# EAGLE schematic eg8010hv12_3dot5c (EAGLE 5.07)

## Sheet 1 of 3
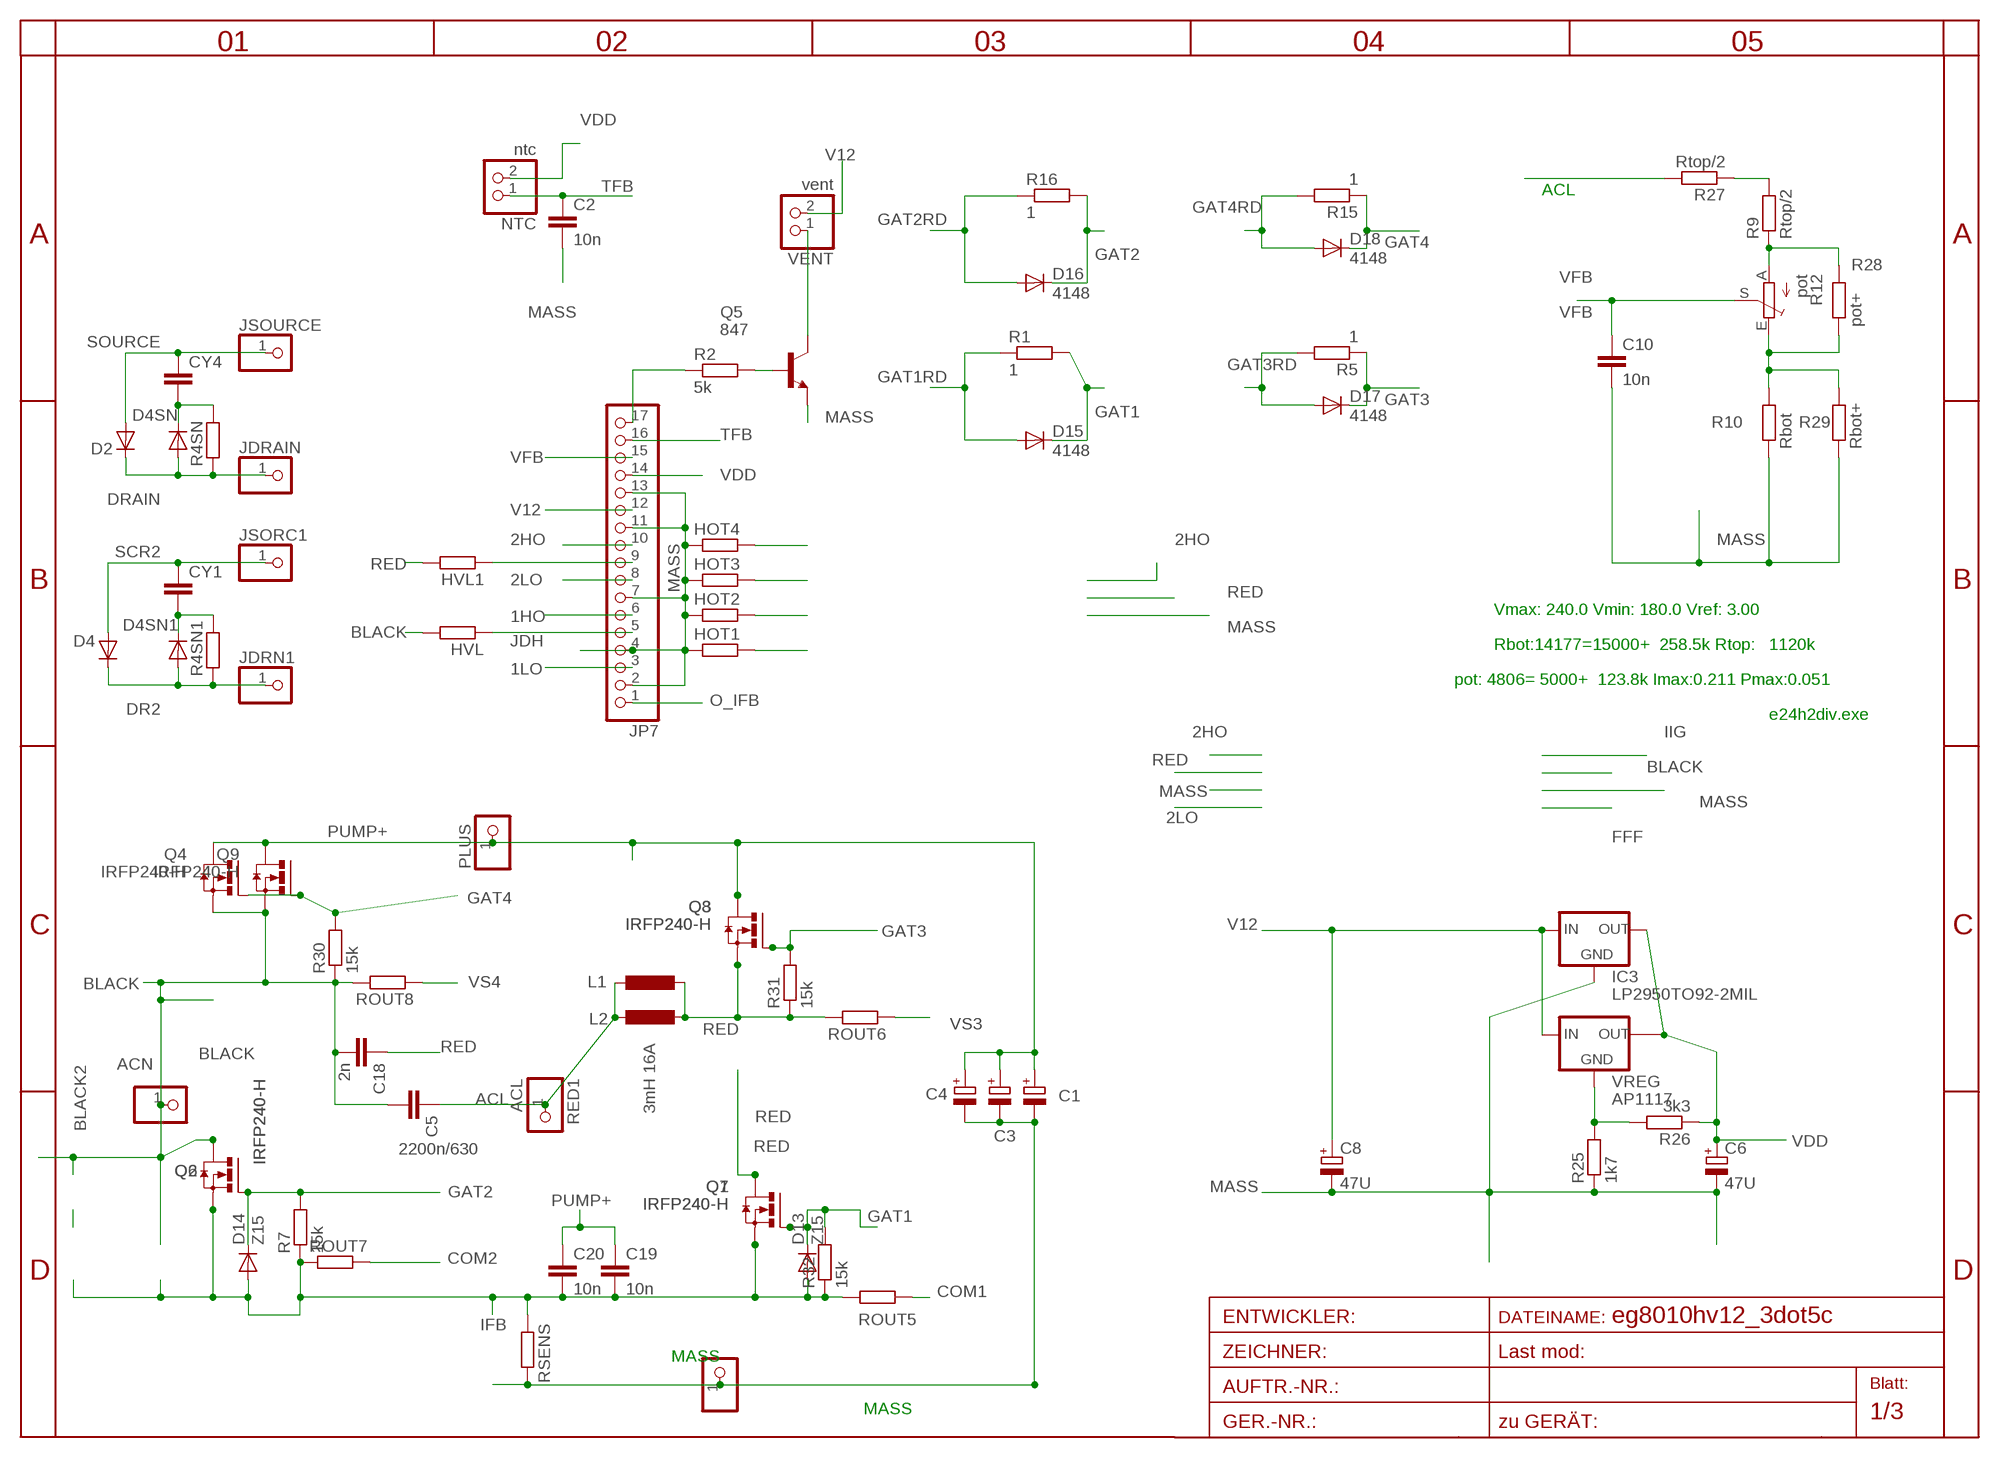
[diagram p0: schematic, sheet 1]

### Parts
BLACK2  ACN  PINHD-1X12MM3  [1X2MM3]
C1  CPOL-EUE5-13  [E5-13]
C2  10n  C-EUC0805  [C0805]
C3  CPOL-EUE5-13  [E5-13]
C4  CPOL-EUE5-13  [E5-13]
C5  2200n/630  C-EU275-173X316  [C275-173X316]
C6  47U  CPOL-EUSMCA  [SMC_A]
C8  47U  CPOL-EUSMCA  [SMC_A]
C10  10n  C-EUC0805  [C0805]
C18  2n  C-EU050-024X044  [C050-024X044]
C19  10n  C-EU050-024X044  [C050-024X044]
C20  10n  C-EU050-024X044  [C050-024X044]
CY1  CXXC10B5  [XC10B5]
CY4  CXXC10B5  [XC10B5]
D2  DIODE-SMC  [SMC]
D4  DIODE-SMC  [SMC]
D4SN  DIODE-P1-10  [P1-10]
D4SN1  DIODE-P1-10  [P1-10]
D13  Z15  DIODE-MINIMELF  [MINIMELF]
D14  Z15  DIODE-MINIMELF  [MINIMELF]
D15  4148  DIODE-MINIMELF  [MINIMELF]
D16  4148  DIODE-MINIMELF  [MINIMELF]
D17  4148  DIODE-MINIMELF  [MINIMELF]
D18  4148  DIODE-MINIMELF  [MINIMELF]
HOT1  R-EU_R0805  [R0805]
HOT2  R-EU_R0805  [R0805]
HOT3  R-EU_R0805  [R0805]
HOT4  R-EU_R0805  [R0805]
HVL  R-EU_R1005  [R1005]
HVL1  R-EU_R1005  [R1005]
IC3  LP2950TO92-2MIL  [TO92-2MIL]
JDRAIN  PINHD-1X11MM0  [1X1MM0]
JDRN1  PINHD-1X11MM0  [1X1MM0]
JP7  PINHD-1X17  [1X17]
JSORC1  PINHD-1X11MM0  [1X1MM0]
JSOURCE  PINHD-1X11MM0  [1X1MM0]
L1  L-EU4.13  [0204/13]
L2  3mH 16A  L-EURNG  [RING]
MINUS  PINHD-1X12MM3  [1X2MM3]
NTC  ntc  PINHD-1X2STR  [1X02]
PLUS  PINHD-1X12MM3  [1X2MM3]
Q1  IRFP240-H  [TO247BH]
Q2  IRFP240-H  [TO247BH]
Q3  IRFP240-H  [TO247BH]
Q4  IRFP240-H  [TO247BH]
Q5  847  BC847SMD  [SOT23]
Q6  IRFP240-H  [TO247BH]
Q7  IRFP240-H  [TO247BH]
Q8  IRFP240-H  [TO247BH]
Q9  IRFP240-H  [TO247BH]
R1  1  R-EU_R2512  [R2512]
R2  5k  R-EU_R0805  [R0805]
R4SN  R-EU_0207/10  [0207/10]
R4SN1  R-EU_0207/10  [0207/10]
R5  1  R-EU_R2512  [R2512]
R7  15k  R-EU_R1206  [R1206]
R9  Rtop/2  R-EU_R1206  [R1206]
R10  Rbot  R-EU_R0805  [R0805]
R12  pot  TRIM_EU-B64Y  [B64Y]
R15  1  R-EU_R2512  [R2512]
R16  1  R-EU_R2512  [R2512]
R25  1k7  R-EU_R0805  [R0805]
R26  3k3  R-EU_R0805  [R0805]
R27  Rtop/2  R-EU_R1206  [R1206]
R28  pot+  R-EU_R0805  [R0805]
R29  Rbot+  R-EU_R0805  [R0805]
R30  15k  R-EU_R1206  [R1206]
R31  15k  R-EU_R1206  [R1206]
R32  15k  R-EU_R1206  [R1206]
RED1  ACL  PINHD-1X12MM3  [1X2MM3]
ROUT5  R-EU_R2512  [R2512]
ROUT6  R-EU_R2512  [R2512]
ROUT7  R-EU_R2512  [R2512]
ROUT8  R-EU_R2512  [R2512]
RSENS  R-EU_WIRE  [WIRE]
VENT  vent  PINHD-1X2STR  [1X02]
VREG  AP1117  [SOT223]

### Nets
1HO: HOT2.2 JP7.6 ; also sheet 3
1LO: HOT1.2 JP7.3 ; also sheet 3
2HO: HOT4.2 JP7.10 ; also sheet 3
2LO: HOT3.2 JP7.8 ; also sheet 3
ACL: C5.1 L1.1 L2.2 R27.2 RED1.1
BLACK: BLACK2.1 C5.2 C18.2 HVL.2 Q2.D Q4.S Q6.D Q9.S R30.1 ROUT8.2
COM1: ROUT5.1 ; also sheet 3
COM2: ROUT7.2 ; also sheet 3
DFG: HVL1.1 JP7.9
DR2: D4.C D4SN1.A JDRN1.1 R4SN1.1
DRAIN: D2.C D4SN.A JDRAIN.1 R4SN.1
GAT1: D13.C D15.C Q1.G Q7.G R1.2 R32.2
GAT1RD: D15.A R1.1 ; also sheet 3
GAT2: D14.C D16.C Q2.G Q6.G R7.2 R16.2
GAT2RD: D16.A R16.1 ; also sheet 3
GAT3: D17.C Q3.G Q8.G R5.1 R31.2
GAT3RD: D17.A R5.2 ; also sheet 3
GAT4: D18.C Q4.G Q9.G R15.1 R30.2
GAT4RD: D18.A R15.2 ; also sheet 3
IFB: C19.2 C20.2 D13.A D14.A Q1.S Q2.S Q6.S Q7.S R7.1 R32.1 ROUT5.2 ROUT7.1 RSENS.1 ; also sheet 2,3
JDH: HVL.1 JP7.5
MASS: C1.- C2.2 C3.- C4.- C6.- C8.- C10.2 HOT1.1 HOT2.1 HOT3.1 HOT4.1 IC3.2(GND) JP7.2 JP7.4 JP7.7 JP7.11 JP7.13 MINUS.1 Q5.2(E) R10.1 R25.1 R29.1 RSENS.2 ; also sheet 2,3
N$1: Q5.3(C) VENT.1
N$2: Q5.1(B) R2.2
N$3: JP7.17 R2.1
N$17: R25.2 R26.2 VREG.1(GND)
N$23: R9.2 R27.1
N$29: R10.2 R12.E R28.1 R29.2
N$30: R9.1 R12.A R28.2
O_IFB: JP7.1 ; also sheet 3
PUMP+: C1.+ C3.+ C4.+ C19.1 C20.1 PLUS.1 Q3.D Q4.D Q8.D Q9.D ; also sheet 2
RED: C18.1 HVL1.2 L1.2 L2.1 Q1.D Q3.S Q7.D Q8.S R31.1 ROUT6.2
SCR2: CY1.1 D4.A JSORC1.1
SNUB1: CY1.2 D4SN1.C R4SN1.2
SNUB2: CY4.2 D4SN.C R4SN.2
SOURCE: CY4.1 D2.A JSOURCE.1
TFB: C2.1 JP7.16 NTC.1 ; also sheet 2
V12: C8.+ IC3.3(IN) JP7.12 VENT.2 VREG.3(IN) ; also sheet 2,3
VDD: C6.+ IC3.1(OUT) JP7.14 NTC.2 R26.1 VREG.4(TAB) ; also sheet 2
VFB: C10.1 JP7.15 R12.S ; also sheet 2
VS3: ROUT6.1
VS4: ROUT8.1 ; also sheet 3
Unconnected: VREG.2(OUT)

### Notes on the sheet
- Vmax: 240.0 Vmin: 180.0 Vref: 3.00
- Rbot:14177=15000+  258.5k Rtop:   1120k
- pot: 4806= 5000+  123.8k Imax:0.211 Pmax:0.051
- e24h2div.exe

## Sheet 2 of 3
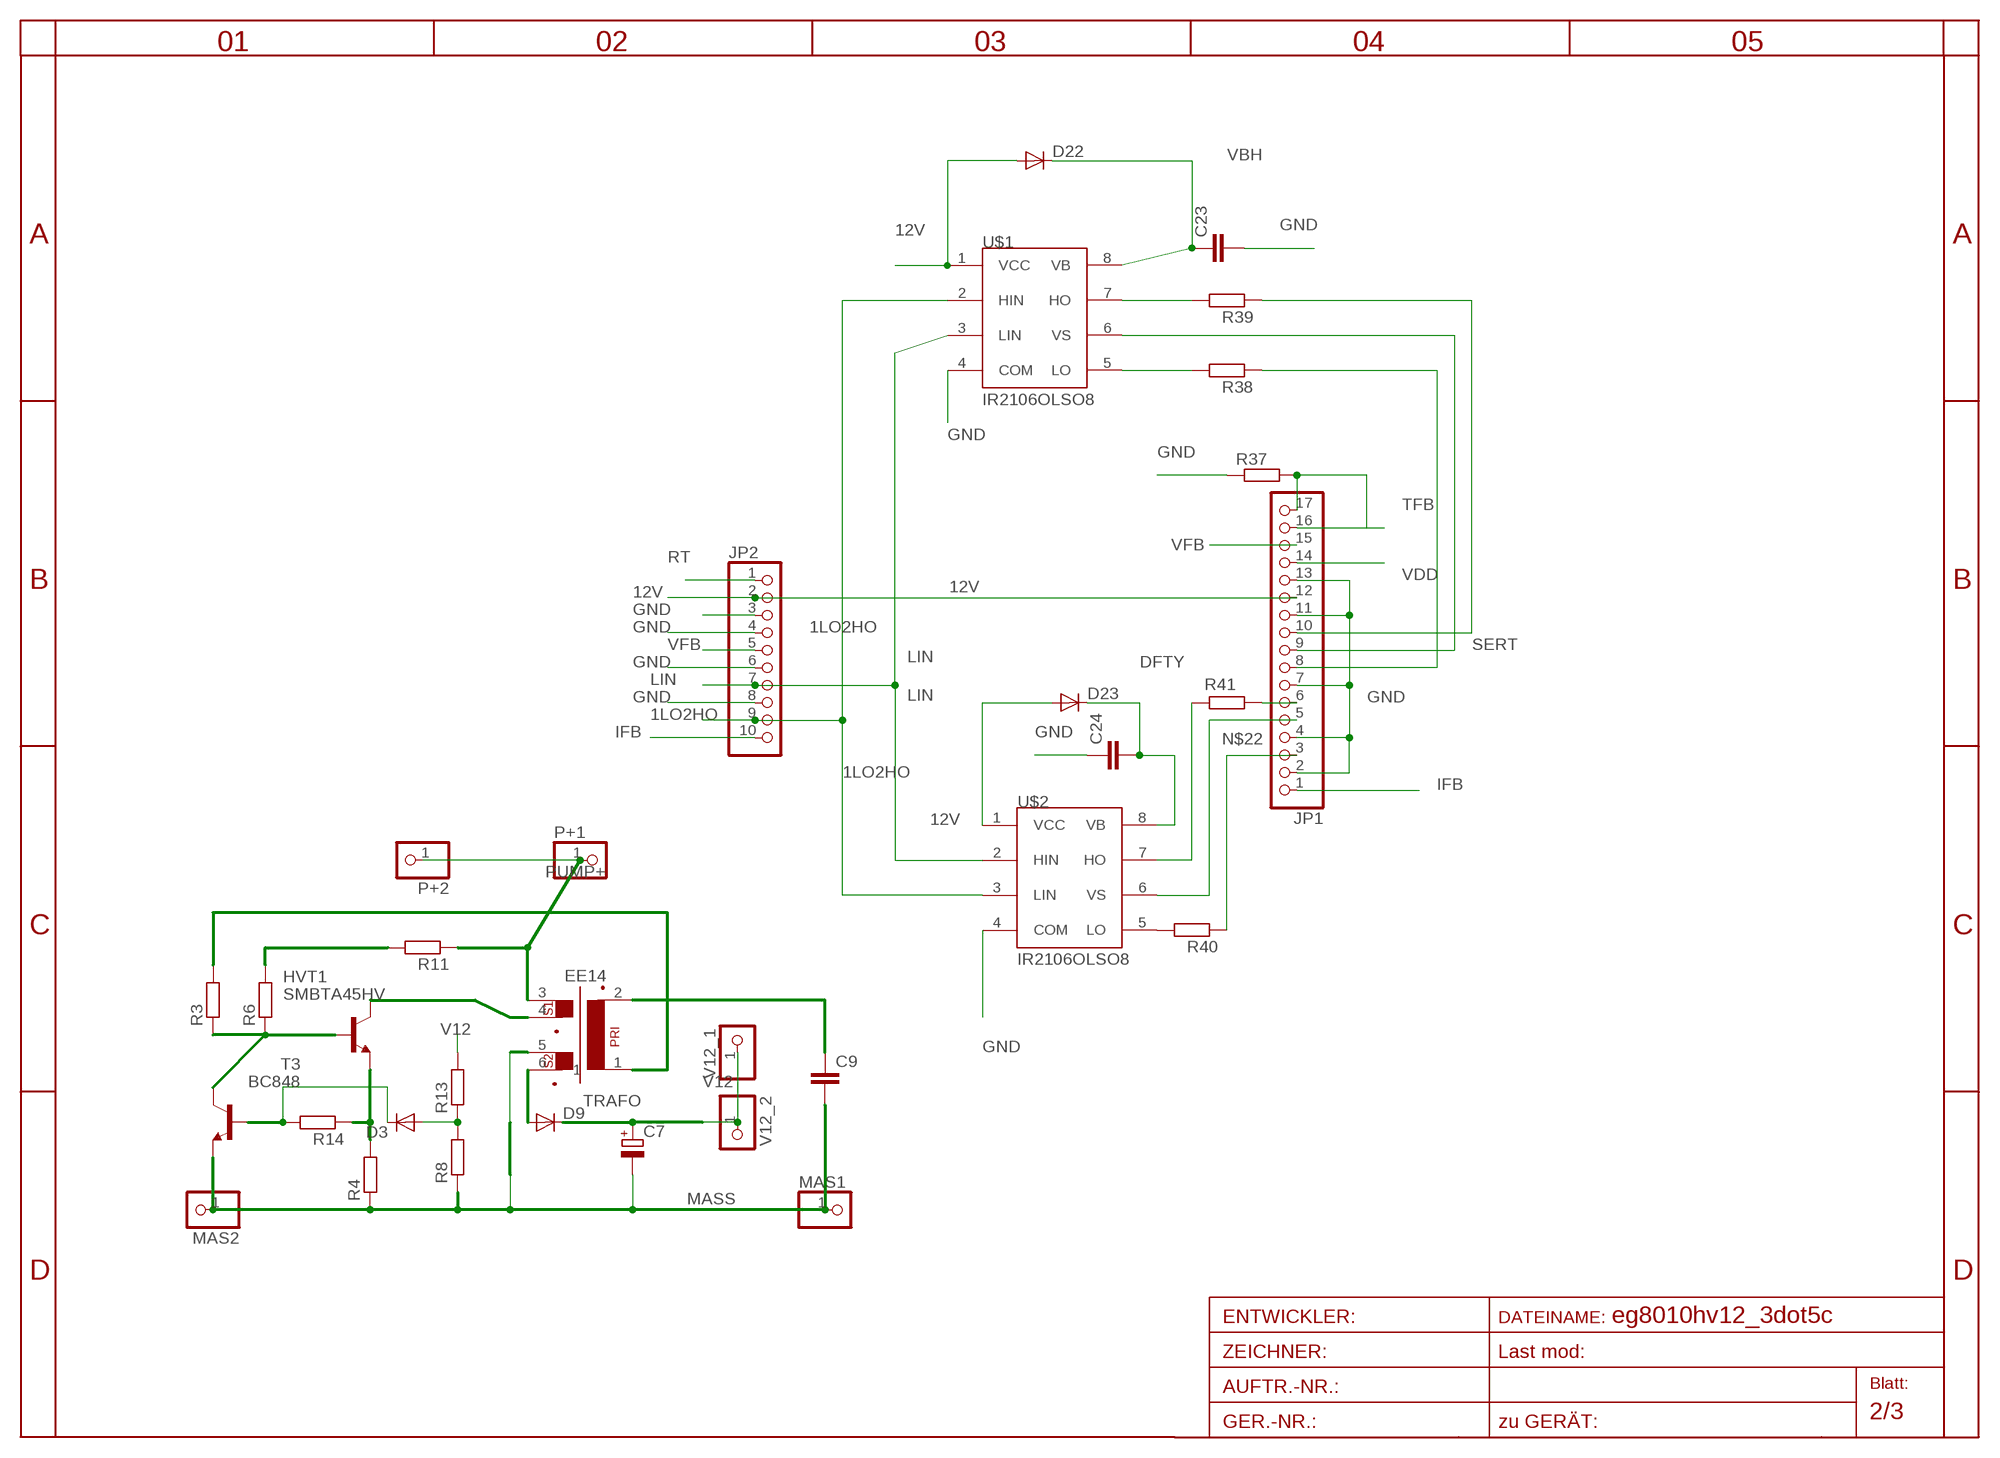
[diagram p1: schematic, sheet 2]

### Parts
C7  CPOL-EUSMCA  [SMC_A]
C9  C-EUC0805  [C0805]
C23  C-EUC1206  [C1206]
C24  C-EUC1206  [C1206]
D3  DIODE-MINIMELF  [MINIMELF]
D9  DIODE-SMA-DO214  [SMA-DO214AC]
D22  DIODE-SMA-DO214  [SMA-DO214AC]
D23  DIODE-SMA-DO214  [SMA-DO214AC]
HVT1  SMBTA45HV  [SOT23HV]
JP1  PINHD-1X17  [1X17]
JP2  PINHD-1X100X05  [1X10]
MAS1  PINHD-1X11X0.4  [1X01]
MAS2  PINHD-1X11X0.4  [1X01]
P+1  PINHD-1X11X0.4  [1X01]
P+2  PINHD-1X11X0.4  [1X01]
R3  R-EU_R0805  [R0805]
R4  R-EU_R0805  [R0805]
R6  R-EU_R1206  [R1206]
R8  R-EU_R0805  [R0805]
R11  R-EU_R1206  [R1206]
R13  R-EU_R0805  [R0805]
R14  R-EU_R0805  [R0805]
R37  R-EU_0204/2V  [0204V]
R38  R-EU_0204/2V  [0204V]
R39  R-EU_0204/2V  [0204V]
R40  R-EU_0204/2V  [0204V]
R41  R-EU_0204/2V  [0204V]
T3  BC848  [SOT23]
TRAFO  EE14  [EE14]
U$1  IR2106OLSO8  [SO8-2]
U$2  IR2106OLSO8  [SO8-2]
V12_1  PINHD-1X11X0.4  [1X01]
V12_2  PINHD-1X11X0.4  [1X01]

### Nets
1LO2HO: JP2.9 U$1.2(HIN) U$2.3(LIN)
12V: D22.A D23.A JP1.12 JP2.2 U$1.1(VCC) U$2.1(VCC)
A: D9.A TRAFO.6
B1C2: HVT1.1(B) R3.1 R6.1 T3.C
BT1: D3.C R14.2 T3.B
C1: HVT1.3(C) TRAFO.4
DFTY: C24.2 D23.K(C) U$2.8(VB)
EB: HVT1.2(E) R4.2 R14.1
GND: C23.2 C24.1 JP1.2 JP1.4 JP1.7 JP1.11 JP1.13 JP2.3 JP2.4 JP2.6 JP2.8 R37.1 U$1.4(COM) U$2.4(COM)
IFB: JP1.1 JP2.10 ; also sheet 1,3
LIN: JP2.7 U$1.3(LIN) U$2.2(HIN)
MASS: C7.- C9.2 MAS1.1 MAS2.1 R4.1 R8.1 T3.E TRAFO.5 ; also sheet 1,3
N$6: R3.2 TRAFO.1
N$7: C9.1 TRAFO.2
N$8: R6.2 R11.2
N$10: D3.A R8.2 R13.1
N$15: JP1.3 R40.1
N$19: R41.2 U$2.7(HO)
N$21: JP1.8 R38.1
N$22: JP1.5 U$2.6(VS)
N$27: JP1.10 R39.1
N$32: R38.2 U$1.5(LO)
N$33: R39.2 U$1.7(HO)
N$34: JP1.6 R41.1
N$35: R40.2 U$2.5(LO)
PUMP+: P+1.1 P+2.1 R11.1 TRAFO.3 ; also sheet 1
RT: JP2.1
SERT: JP1.9 U$1.6(VS)
TFB: JP1.16 JP1.17 R37.2 ; also sheet 1
V12: C7.+ D9.K(C) R13.2 V12_1.1 V12_2.1 ; also sheet 1,3
VBH: C23.1 D22.K(C) U$1.8(VB)
VDD: JP1.14 ; also sheet 1
VFB: JP1.15 JP2.5 ; also sheet 1

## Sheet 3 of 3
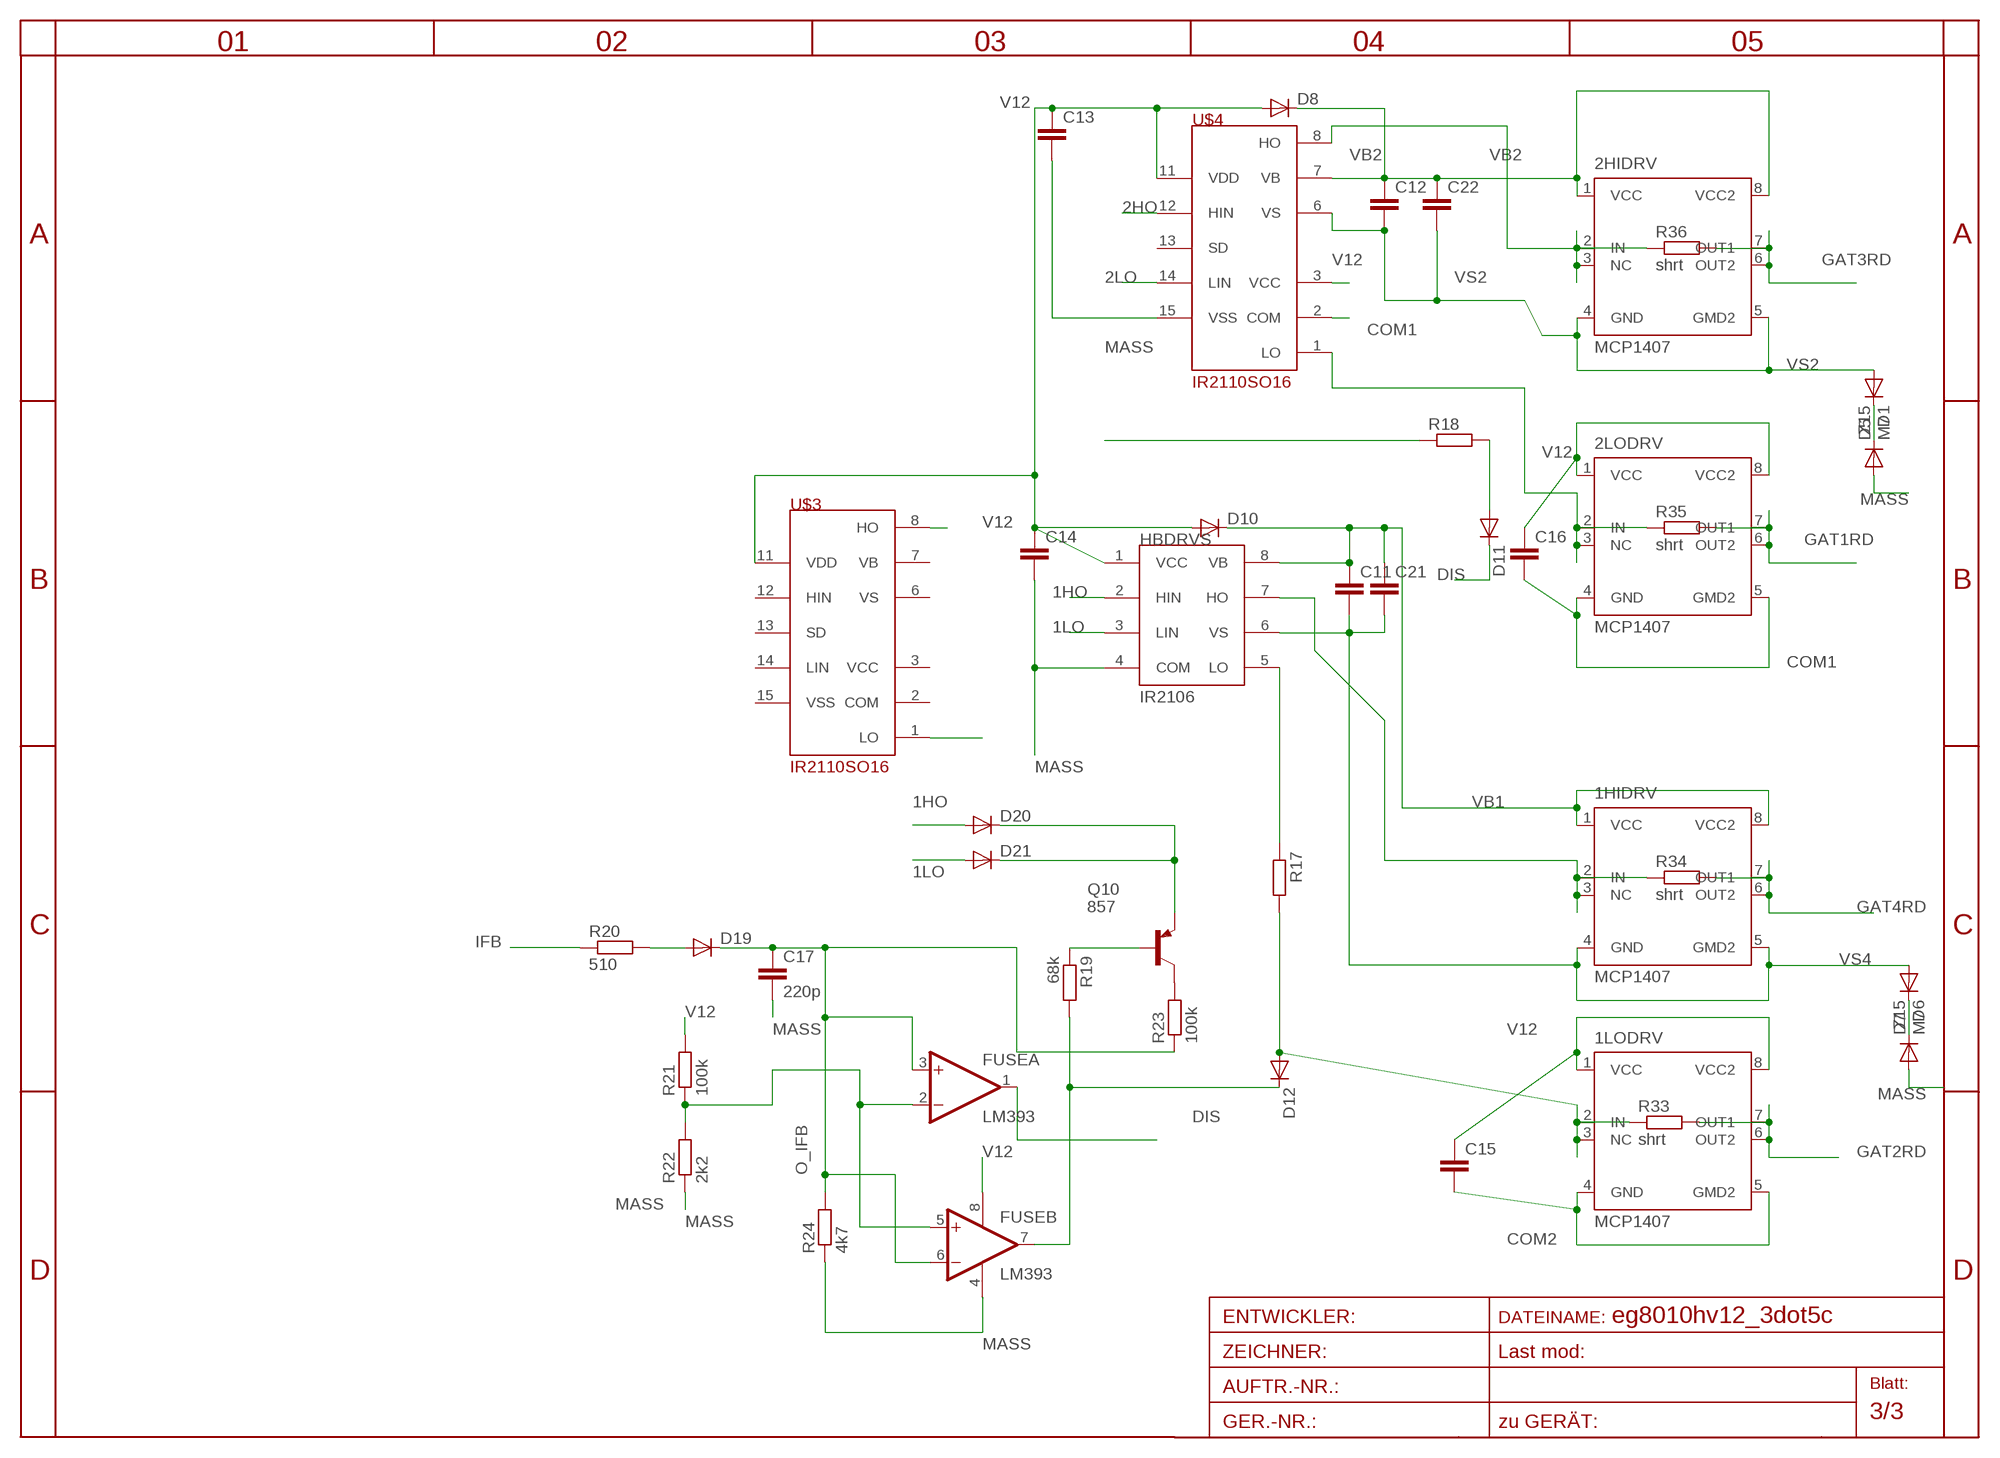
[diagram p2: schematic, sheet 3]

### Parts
1HIDRV  MCP1407  [SO-08M]
1LODRV  MCP1407  [SO-08M]
2HIDRV  MCP1407  [SO-08M]
2LODRV  MCP1407  [SO-08M]
C11  C-EUC058MLCC  [C058-020X040]
C12  C-EUC058MLCC  [C058-020X040]
C13  C-EUC1206  [C1206]
C14  C-EUC1206  [C1206]
C15  C-EUC1206  [C1206]
C16  C-EUC1206  [C1206]
C17  220p  C-EUC0805  [C0805]
C21  C-EUC1206  [C1206]
C22  C-EUC1206  [C1206]
D1  Z15  DIODE-MINIMELF  [MINIMELF]
D5  M7  DIODE-SMA-DO214  [SMA-DO214AC]
D6  Z15  DIODE-MINIMELF  [MINIMELF]
D7  M7  DIODE-SMA-DO214  [SMA-DO214AC]
D8  DIODE-SMA-DO214  [SMA-DO214AC]
D10  DIODE-SMA-DO214  [SMA-DO214AC]
D11  DIODE-MINIMELF  [MINIMELF]
D12  DIODE-MINIMELF  [MINIMELF]
D19  DIODE-SOT23  [SOT23]
D20  DIODE-SOT23  [SOT23]
D21  DIODE-SOT23  [SOT23]
FUSE  LM393  LM358D  [SO08]
HBDRVS  IR2106  [SO8-5]
Q10  857  BC857ALT1SMD  [SOT23-BEC]
R17  R-EU_0207-17  [0207/17]
R18  R-EU_0204/5  [0204/5]
R19  68k  R-EU_R0805  [R0805]
R20  510  R-EU_R0805  [R0805]
R21  100k  R-EU_R0805  [R0805]
R22  2k2  R-EU_R0805  [R0805]
R23  100k  R-EU_R0805  [R0805]
R24  4k7  R-EU_R0805  [R0805]
R33  shrt  R-EU_R1206  [R1206]
R34  shrt  R-EU_R1206  [R1206]
R35  shrt  R-EU_R1206  [R1206]
R36  shrt  R-EU_R1206  [R1206]
U$3  IR2110SO16  [SO16DW]
U$4  IR2110SO16  [SO16DW]

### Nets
1HO: D20.1(A) HBDRVS.2(HIN) ; also sheet 1
1LO: D21.1(A) HBDRVS.3(LIN) ; also sheet 1
2HO: U$4.12(HIN) ; also sheet 1
2LO: U$4.14(LIN) ; also sheet 1
COM1: 2LODRV.4(GND) 2LODRV.5(GMD2) C16.2 U$4.2(COM) ; also sheet 1
COM2: 1LODRV.4(GND) 1LODRV.5(GMD2) C15.2 ; also sheet 1
DIS: D11.C D12.C FUSE.7(B:OUT) R19.2
GAT1RD: 2LODRV.6(OUT2) 2LODRV.7(OUT1) R35.2 ; also sheet 1
GAT2RD: 1LODRV.6(OUT2) 1LODRV.7(OUT1) R33.2 U$3.1(LO) ; also sheet 1
GAT3RD: 2HIDRV.6(OUT2) 2HIDRV.7(OUT1) R36.2 ; also sheet 1
GAT4RD: 1HIDRV.6(OUT2) 1HIDRV.7(OUT1) R34.2 U$3.8(HO) ; also sheet 1
IFB: R20.1 ; also sheet 1,2
MASS: C13.2 C14.2 C17.2 D5.A D7.A FUSE.4(P:V-) HBDRVS.4(COM) R22.1 R24.1 U$4.15(VSS) ; also sheet 1,2
N$4: R18.1
N$5: 1LODRV.2(IN) 1LODRV.3(NC) D12.A R17.2 R33.1
N$9: FUSE.2(A:-IN) FUSE.5(B:+IN) R21.1 R22.2
N$11: HBDRVS.5(LO) R17.1
N$12: 2HIDRV.2(IN) 2HIDRV.3(NC) R36.1 U$4.8(HO)
N$13: 1HIDRV.2(IN) 1HIDRV.3(NC) HBDRVS.7(HO) R34.1
N$14: D19.1(A) R20.2
N$16: 2LODRV.2(IN) 2LODRV.3(NC) R35.1 U$4.1(LO)
N$18: D20.3(C) D21.3(C) Q10.E
N$20: D1.C D5.K(C)
N$24: D6.C D7.K(C)
N$25: Q10.B R19.1
N$26: Q10.C R23.2
N$36: D11.A R18.2
O_IFB: C17.1 D19.3(C) FUSE.3(A:+IN) FUSE.6(B:-IN) R23.1 R24.2 ; also sheet 1
SD: FUSE.1(A:OUT)
V12: 1LODRV.1(VCC) 1LODRV.8(VCC2) 2LODRV.1(VCC) 2LODRV.8(VCC2) C13.1 C14.1 C15.1 C16.1 D8.A D10.A FUSE.8(P:V+) HBDRVS.1(VCC) R21.2 U$3.11(VDD) U$4.3(VCC) U$4.11(VDD) ; also sheet 1,2
VB1: 1HIDRV.1(VCC) 1HIDRV.8(VCC2) C11.1 C21.1 D10.K(C) HBDRVS.8(VB)
VB2: 2HIDRV.1(VCC) 2HIDRV.8(VCC2) C12.1 C22.1 D8.K(C) U$4.7(VB)
VS2: 2HIDRV.4(GND) 2HIDRV.5(GMD2) C12.2 C22.2 D1.A U$4.6(VS)
VS4: 1HIDRV.4(GND) 1HIDRV.5(GMD2) C11.2 C21.2 D6.A HBDRVS.6(VS) ; also sheet 1
Unconnected: U$3.2(COM) U$3.3(VCC) U$3.6(VS) U$3.7(VB) U$3.12(HIN) U$3.13(SD) U$3.14(LIN) U$3.15(VSS) U$4.13(SD)

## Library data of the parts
1HIDRV 1LODRV 2HIDRV 2LODRV = microchip:MCP1407
BLACK2 JDRAIN JDRN1 JSORC1 JSOURCE MAS1 MAS2 MINUS P+1 P+2 PLUS RED1 V12_1 V12_2 = pinhead:PINHD-1X1: PIN HEADER
C1 C3 C4 C6-C8 = rcl:CPOL-EU: POLARIZED CAPACITOR, European symbol
C2 C5 C9-C24 = rcl:C-EU: CAPACITOR, European symbol
CY1 CY4 = rcl:CX: X CAPACITOR
D1-D4 D4SN D4SN1 D5-D23 = diode:DIODE-: DIODE
FUSE = linear:LM358: OP AMP also LM158; LM258; LM2904 Source: http://cache.national.com/ds/LM/LM158.pdf
HBDRVS U$1 U$2 = irf-2:IR2106
HOT1-HOT4 HVL HVL1 R1-R4 R4SN R4SN1 R5-R8 R11 R13-R24 R30-R41 ROUT5-ROUT8 RSENS = rcl:R-EU_: RESISTOR, European symbol
HVT1 = transistor-npn:SMBTA45
IC3 = v-reg:LP2950?*: Source: http://cache.national.com/ds/LP/LP2950.pdf
JP1 JP7 = pinhead:PINHD-1X17: PIN HEADER
JP2 = pinhead:PINHD-1X10: PIN HEADER
L1 L2 = rcl:L-EU: INDUCTOR, European symbol
NTC VENT = pinhead:PINHD-1X2: PIN HEADER
Q1-Q4 Q6-Q9 = transistor-power:IRFP240: HEXFET Power MosFet Source: http://www.irf.com/
Q5 = transistor-npn:BC847*: NPN Transistor
Q10 = transistor-pnp:BC857*: PNP Transistror
R9 R10 R25-R29 = rcl-2:R-EU_: RESISTOR, European symbol
R12 = pot:TRIM_EU-: POTENTIOMETER
T3 = transistor:BC848: NPN TRANSISTOR
TRAFO = trafo:EE14
U$3 U$4 = ir2112:IR2110
VREG = v-reg:AP1117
